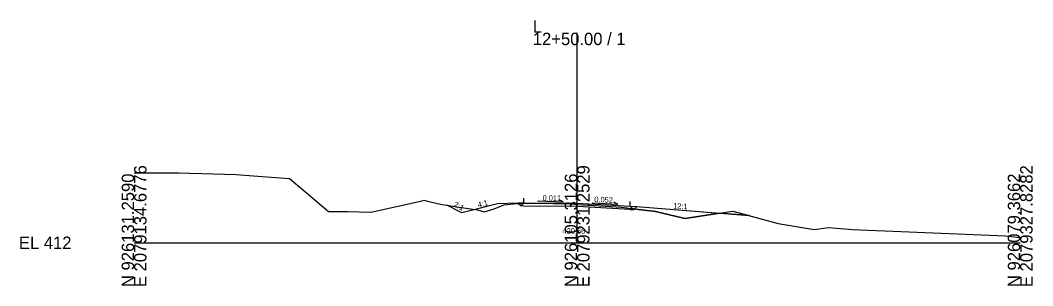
# Model space of a CAD drawing. Extents: x -26 to 10503, y -10 to 9546.
# Drawn here: x -25.7 to 202.8, y 4990.3 to 5050.2 of the extents above; entities that cross this region are included whole.
import ezdxf

# ---------------------------------------------------------------- set-up
doc = ezdxf.new("R2010")
doc.units = 0
for name, color, linetype in [('Default', 7, 'Continuous'), ('Exist XS Center Line Elevation Label', 7, 'Continuous'), ('Exist XS Ground Line', 7, 'Continuous'), ('Old_Level_63', 7, 'Continuous'), ('Prop XS Ditch Slope Text', 7, 'Continuous'), ('Prop XS Dump Level', 7, 'Continuous'), ('Prop XS EOT Tick Mark', 7, 'Continuous'), ('Prop XS Finish Grade', 7, 'Continuous'), ('Prop XS Finish Grade Earthwork', 7, 'Continuous'), ('Prop XS Finish Grade Pavement', 7, 'Continuous'), ('Prop XS Pvmt Edge Slope', 7, 'Continuous'), ('Prop XS SE Text', 7, 'Continuous'), ('Prop XS Side Slope Text', 7, 'Continuous'), ('Prop XS Subgrade Earthwork', 7, 'Continuous')]:
    doc.layers.add(name, color=color, linetype=linetype)

msp = doc.modelspace()

# ---------------------------------------------------------------- linework, layer by layer
at = {"layer": 'Default'}
for points in [[(70.58, 5008.45), (73.34, 5008.01), (77.01, 5007.49), (74, 5006.74)], [(77.01, 5007.49), (77.51, 5007.42), (79.02, 5006.96), (81.02, 5007.57), (83.57, 5008.53), (85.64, 5008.76), (86.67, 5008.88), (86.59, 5008.96), (82, 5008.74)], [(112, 5007.52), (100, 5008.14), (88, 5008.28), (87.26, 5008.29), (86.67, 5008.88), (87.4, 5008.96), (94.59, 5008.87), (98.77, 5008.75), (100, 5008.66), (102.56, 5008.49), (108.84, 5008.11), (109.93, 5008.03), (110.61, 5007.97), (112.94, 5007.63), (112.79, 5007.48)], [(113.46, 5008.16), (132.12, 5006.67), (124.82, 5005.55), (124.37, 5005.45), (124.04, 5005.53), (117.67, 5007.03), (113.24, 5007.59), (112.94, 5007.63)], [(132.12, 5006.67), (135.18, 5007.13), (138.86, 5006.13)]]:
    msp.add_lwpolyline(points, close=True, dxfattribs=at)
at = {"layer": 'Exist XS Ground Line'}
for p, q in [((0, 5015.79), (10.13, 5015.73)), ((10.13, 5015.73), (23.03, 5015.36)), ((23.03, 5015.36), (27.94, 5015)), ((27.94, 5015), (35.09, 5014.46)), ((35.09, 5014.46), (38.85, 5011.35)), ((38.85, 5011.35), (43.91, 5007.03)), ((53.44, 5006.93), (65.03, 5009.47)), ((65.03, 5009.47), (65.42, 5009.58)), ((65.42, 5009.58), (65.94, 5009.46)), ((65.94, 5009.46), (69.16, 5008.67)), ((69.16, 5008.67), (73.34, 5008.01)), ((73.34, 5008.01), (77.51, 5007.42)), ((77.51, 5007.42), (79.02, 5006.96)), ((79.02, 5006.96), (81.02, 5007.57)), ((81.02, 5007.57), (83.57, 5008.53)), ((83.57, 5008.53), (85.64, 5008.76)), ((85.64, 5008.76), (87.4, 5008.96)), ((87.4, 5008.96), (94.59, 5008.87)), ((94.59, 5008.87), (98.77, 5008.75)), ((98.77, 5008.75), (100, 5008.66)), ((100, 5008.66), (102.56, 5008.49)), ((102.56, 5008.49), (108.84, 5008.11)), ((108.84, 5008.11), (109.93, 5008.03)), ((109.93, 5008.03), (110.61, 5007.97)), ((110.61, 5007.97), (113.24, 5007.59)), ((113.24, 5007.59), (117.67, 5007.03)), ((43.91, 5007.03), (48.18, 5007.02)), ((48.18, 5007.02), (53.44, 5006.93)), ((117.67, 5007.03), (124.04, 5005.53)), ((124.04, 5005.53), (124.37, 5005.45)), ((124.37, 5005.45), (124.82, 5005.55)), ((124.82, 5005.55), (135.18, 5007.13)), ((135.18, 5007.13), (145.35, 5004.35)), ((145.35, 5004.35), (153.53, 5002.99)), ((153.53, 5002.99), (156.77, 5003.42)), ((156.77, 5003.42), (162.15, 5003.01)), ((162.15, 5003.01), (196.67, 5001.55)), ((196.67, 5001.55), (200, 5001.2))]:
    msp.add_line(p, q, dxfattribs=at)
at = {"layer": 'Old_Level_63'}
for p, q in [((100, 5000), (100, 5047.37)), ((0, 5000), (100, 5000)), ((100, 5000), (200, 5000))]:
    msp.add_line(p, q, dxfattribs=at)
at = {"layer": 'Prop XS EOT Tick Mark'}
for p, q in [((88, 5009.03), (88, 5010.03)), ((112, 5008.27), (112, 5009.27))]:
    msp.add_line(p, q, dxfattribs=at)
at = {"layer": 'Prop XS Finish Grade'}
for p, q in [((88, 5009.03), (86.59, 5008.96)), ((112, 5008.27), (113.46, 5008.16))]:
    msp.add_line(p, q, dxfattribs=at)
at = {"layer": 'Prop XS Finish Grade Earthwork'}
for p, q in [((74, 5006.74), (70.58, 5008.45)), ((82, 5008.74), (74, 5006.74)), ((86.59, 5008.96), (82, 5008.74)), ((113.46, 5008.16), (138.86, 5006.13))]:
    msp.add_line(p, q, dxfattribs=at)
at = {"layer": 'Prop XS Finish Grade Pavement'}
for p, q in [((88, 5009.03), (100, 5008.89)), ((100, 5008.89), (112, 5008.27))]:
    msp.add_line(p, q, dxfattribs=at)
at = {"layer": 'Prop XS Pvmt Edge Slope'}
for p, q in [((88, 5009.03), (87.26, 5008.29)), ((112, 5008.27), (112.79, 5007.48))]:
    msp.add_line(p, q, dxfattribs=at)
at = {"layer": 'Prop XS SE Text'}
for points in [[(91.07, 5009.48), (96.83, 5009.21), (95.98, 5009.67)], [(103.4, 5008.99), (109.16, 5008.71), (108.3, 5009.17)]]:
    msp.add_lwpolyline(points, dxfattribs=at)
at = {"layer": 'Prop XS Subgrade Earthwork'}
for p, q in [((87.26, 5008.29), (86.59, 5008.96)), ((88, 5008.28), (87.26, 5008.29)), ((100, 5008.14), (88, 5008.28)), ((112, 5007.52), (100, 5008.14)), ((112, 5007.52), (112.79, 5007.48)), ((112.79, 5007.48), (113.46, 5008.16))]:
    msp.add_line(p, q, dxfattribs=at)

# ---------------------------------------------------------------- texts
at = {"layer": 'Exist XS Center Line Elevation Label'}
msp.add_text('420.66', height=1.25, rotation=360, dxfattribs=at).set_placement((96.71, 5002.04))
at = {"layer": 'Old_Level_63'}
for s, p in [('L', (90, 5047.37)), ('12+50.00 / 1', (90, 5044.57)), ('EL 412', (-26, 4998.6))]:
    msp.add_text(s, height=2.8, dxfattribs=at).set_placement(p)
for s, p in [('E 2079134.6776', (2.8, 4990)), ('E 2079231.2529', (102.8, 4990)), ('E 2079327.8282', (202.8, 4990)), ('N 926131.2590', (0, 4990)), ('N 926105.3126', (100, 4990)), ('N 926079.3662', (200, 4990))]:
    msp.add_text(s, height=2.8, rotation=90, dxfattribs=at).set_placement(p)
at = {"layer": 'Prop XS Ditch Slope Text'}
for s, rotation, p in [('4:1', 14.0362, (77.71, 5007.91)), ('12:1', 356.5563, (121.65, 5007.74))]:
    msp.add_text(s, height=1.25, rotation=rotation, dxfattribs=at).set_placement(p)
at = {"layer": 'Prop XS Dump Level'}
msp.add_text('Case1', height=0.04, dxfattribs=at).set_placement((120, 5007.59))
at = {"layer": 'Prop XS SE Text'}
for s, rotation, p in [('0.011', 359.3411, (92.19, 5009.48)), ('0.052', 357.0519, (103.86, 5009.19))]:
    msp.add_text(s, height=1.25, rotation=rotation, dxfattribs=at).set_placement(p)
at = {"layer": 'Prop XS Side Slope Text'}
msp.add_text('2:1', height=1.25, rotation=333.4349, dxfattribs=at).set_placement((72.02, 5008.25))

doc.saveas('drawing.dxf')
